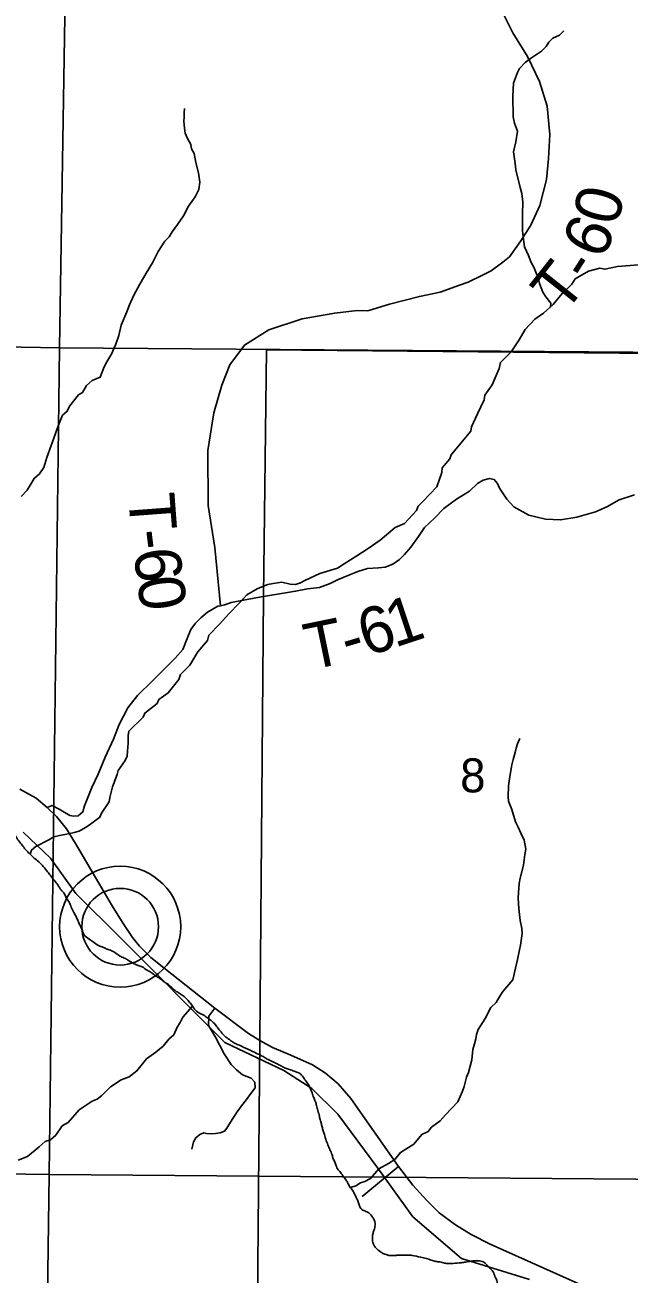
# Model space of a CAD drawing. Extents: x 0 to 191, y 0 to 55.
# Drawn here: x 148.459 to 148.831, y 19.371 to 20.139 of the extents above; entities that cross this region are included whole.
import ezdxf

# ---------------------------------------------------------------- set-up
doc = ezdxf.new("R2010")
doc.units = 0
for name, color, linetype in [('GM_X_Corporation', 7, 'Continuous'), ('GM_X_Minor_River', 7, 'Continuous'), ('GM_X_Rail_Line', 7, 'Continuous'), ('GM_X_Section_Text', 7, 'Continuous'), ('GM_X_State_Route', 7, 'Continuous'), ('GM_X_Township_Road', 7, 'Continuous'), ('GM_X_Township_Road_Text', 7, 'Continuous'), ('GM_X_Unincorporated', 7, 'Continuous'), ('GM_X_Unincorporated_Location', 7, 'Continuous')]:
    doc.layers.add(name, color=color, linetype=linetype)

msp = doc.modelspace()

# ---------------------------------------------------------------- linework, layer by layer
at = {"layer": 'GM_X_Corporation'}
msp.add_lwpolyline([(149.91399, 21.66502), (149.90793, 21.52064), (149.51981, 21.52878), (149.51691, 21.19595), (149.51218, 20.83281), (149.50627, 20.43118), (149.50476, 20.23346), (149.50131, 20.01186), (149.50163, 19.93083), (149.34339, 19.93301), (149.01689, 19.93705), (148.9116, 19.93663), (148.60782, 19.9395), (148.60599, 19.78812), (148.60369, 19.51507), (148.60074, 19.16895), (148.59988, 18.92019), (148.47736, 18.92075), (148.46737, 18.92047), (148.27305, 18.92256)], dxfattribs=at)
for points in [[(147.98029, 20.45945), (148.48878, 20.45041), (148.48051, 19.94079), (147.97486, 19.94949)], [(148.48878, 20.45041), (148.99652, 20.44079), (148.99576, 19.93695), (148.48051, 19.94079)], [(148.46264, 18.61761), (150.07549, 18.61761), (150.07549, 20.00272), (149.87411, 20.00453), (149.74513, 20.00707), (149.50131, 20.01186), (149.50163, 19.93083), (149.34339, 19.93301), (149.01689, 19.93705), (148.9116, 19.93663), (148.60782, 19.9395), (148.60599, 19.78812), (148.60369, 19.51507), (148.60074, 19.16895), (148.59988, 18.92019), (148.47736, 18.92075), (148.46737, 18.92047)], [(147.97486, 19.94949), (148.48051, 19.94079), (148.47431, 19.43234), (147.97418, 19.43959)], [(148.48051, 19.94079), (148.99576, 19.93695), (148.98937, 19.42831), (148.47431, 19.43234)], [(147.97418, 19.43959), (148.47431, 19.43234), (148.4672, 18.92122), (147.9684, 18.92831)], [(148.47431, 19.43234), (148.98937, 19.42831), (148.98207, 18.917), (148.4672, 18.92122)]]:
    msp.add_lwpolyline(points, close=True, dxfattribs=at)
at = {"layer": 'GM_X_Minor_River'}
for points in [[(148.78237, 19.96581), (148.7826, 19.96813), (148.77951, 19.97208), (148.77776, 19.97491), (148.7756, 19.9804), (148.77499, 19.98324), (148.77224, 19.99043), (148.77049, 19.99326), (148.76891, 19.99761), (148.76638, 20.0029), (148.7655, 20.01069), (148.76528, 20.01316), (148.76521, 20.01791), (148.76532, 20.02305), (148.76541, 20.03028), (148.76476, 20.03559), (148.76376, 20.03938), (148.76114, 20.05019), (148.7607, 20.05417), (148.75965, 20.06139), (148.76107, 20.06749), (148.76211, 20.07397), (148.76033, 20.07889), (148.75952, 20.08288), (148.75933, 20.09543), (148.75978, 20.10361), (148.76215, 20.11011), (148.76343, 20.1126), (148.76698, 20.11627), (148.77016, 20.11878), (148.7769, 20.12325), (148.77989, 20.12615), (148.78136, 20.12864), (148.78398, 20.13115), (148.78792, 20.13311), (148.79072, 20.13562)], [(148.45697, 19.8493), (148.4607, 19.85316), (148.46494, 19.86044), (148.46831, 19.86334), (148.4709, 19.86718), (148.47289, 19.87329), (148.47543, 19.88074), (148.47707, 19.88514), (148.47961, 19.89221), (148.48235, 19.89928), (148.48515, 19.9016), (148.48699, 19.90505), (148.49219, 19.91178), (148.49482, 19.91334), (148.49722, 19.91756), (148.50077, 19.92065), (148.50566, 19.92281), (148.50802, 19.92912), (148.50968, 19.93218), (148.51282, 19.93736), (148.5141, 19.94042), (148.5152, 19.9431), (148.51701, 19.94826), (148.51862, 19.95475), (148.5221, 19.96297), (148.52374, 19.96718), (148.5263, 19.97311), (148.52998, 19.97982), (148.53386, 19.98672), (148.53774, 19.99305), (148.54123, 19.99994), (148.5453, 20.00628), (148.5481, 20.00898), (148.54995, 20.01205), (148.5531, 20.01665), (148.5568, 20.02203), (148.55993, 20.02797), (148.56401, 20.03354), (148.56621, 20.03814), (148.5669, 20.04271), (148.56606, 20.04841), (148.56446, 20.05466), (148.56343, 20.06035), (148.56168, 20.06318), (148.56126, 20.06584), (148.55932, 20.06942), (148.55794, 20.07283), (148.55752, 20.07586), (148.55708, 20.08023), (148.55723, 20.08271), (148.55719, 20.08518), (148.55753, 20.08785)], [(148.4626, 19.62934), (148.46339, 19.6319), (148.466, 19.63403), (148.47408, 19.63813), (148.47708, 19.64007), (148.48066, 19.64088), (148.48614, 19.64191), (148.48972, 19.64272), (148.49274, 19.64352), (148.49649, 19.64586), (148.49893, 19.64722), (148.50548, 19.65207), (148.50639, 19.65455), (148.5112, 19.66165), (148.51154, 19.66432), (148.51315, 19.6708), (148.51607, 19.67845), (148.5166, 19.68092), (148.52105, 19.68707), (148.52214, 19.68975), (148.52248, 19.69279), (148.52278, 19.69774), (148.52272, 19.7023), (148.52325, 19.70497), (148.53201, 19.71365), (148.53311, 19.71613), (148.54059, 19.72194), (148.54169, 19.72443), (148.5475, 19.7285), (148.554, 19.73677), (148.5549, 19.73982), (148.56068, 19.7456), (148.56567, 19.75385), (148.57163, 19.76078), (148.57233, 19.76402), (148.57924, 19.77096), (148.58445, 19.77693), (148.59134, 19.78387), (148.59581, 19.78887), (148.60219, 19.79257), (148.60501, 19.79375), (148.60878, 19.79514), (148.61199, 19.79575), (148.61727, 19.79659), (148.6224, 19.79552), (148.62562, 19.79518), (148.62882, 19.79618), (148.63145, 19.79773), (148.64066, 19.80205), (148.65159, 19.80524), (148.65552, 19.80796), (148.6634, 19.81282), (148.67033, 19.81729), (148.67782, 19.82253), (148.68698, 19.83026), (148.69262, 19.83281), (148.70008, 19.84071), (148.70117, 19.84339), (148.70397, 19.84628), (148.71254, 19.85534), (148.71563, 19.86413), (148.71596, 19.86698), (148.72061, 19.87256), (148.72133, 19.87505), (148.72728, 19.88216), (148.73342, 19.88948), (148.73395, 19.89215), (148.73761, 19.90018), (148.74165, 19.9088), (148.74218, 19.91166), (148.74662, 19.91799), (148.75083, 19.92813), (148.75172, 19.93176), (148.75825, 19.93832), (148.76325, 19.94561), (148.76694, 19.95213), (148.7729, 19.9583), (148.77814, 19.96199), (148.78412, 19.96739), (148.7897, 19.97413), (148.79548, 19.97992), (148.7977, 19.98318), (148.80577, 19.98786), (148.81274, 19.98967), (148.81578, 19.98914), (148.8237, 19.99077), (148.83656, 19.9919)], [(148.65944, 19.42433), (148.66284, 19.42542), (148.66566, 19.42717), (148.66829, 19.42816), (148.67186, 19.42992), (148.67688, 19.43588), (148.68289, 19.4392), (148.68683, 19.44172), (148.69017, 19.44595), (148.69842, 19.45101), (148.70345, 19.45697), (148.7072, 19.45892), (148.70925, 19.46142), (148.71468, 19.4653), (148.71784, 19.46914), (148.72548, 19.47704), (148.72841, 19.48354), (148.72932, 19.48641), (148.73074, 19.49232), (148.73203, 19.49519), (148.734, 19.50281), (148.73466, 19.50929), (148.73574, 19.51272), (148.73664, 19.51578), (148.73698, 19.51844), (148.73807, 19.5215), (148.74233, 19.5284), (148.74582, 19.5351), (148.74899, 19.53818), (148.7514, 19.54202), (148.75325, 19.5449), (148.75939, 19.5522), (148.76099, 19.55926), (148.76223, 19.5646), (148.76347, 19.57051), (148.76399, 19.57336), (148.76502, 19.5806), (148.76479, 19.58364), (148.76377, 19.58857), (148.76291, 19.59597), (148.76262, 19.60243), (148.76276, 19.60585), (148.76325, 19.61137), (148.76377, 19.61461), (148.76592, 19.62262), (148.76677, 19.6291), (148.76729, 19.63252), (148.76626, 19.63802), (148.7645, 19.64199), (148.76255, 19.64595), (148.76099, 19.64935), (148.7586, 19.65692), (148.75664, 19.66203), (148.75641, 19.66469), (148.75669, 19.67134), (148.75736, 19.67725), (148.75824, 19.68182), (148.75877, 19.6843), (148.75948, 19.68754), (148.76074, 19.69193), (148.76127, 19.6946), (148.76217, 19.69727), (148.76364, 19.70053)], [(148.56235, 19.53592), (148.55648, 19.52923), (148.55483, 19.52578), (148.55298, 19.5231), (148.55097, 19.51832), (148.54779, 19.51561), (148.54426, 19.51138), (148.53977, 19.50771), (148.53415, 19.50345), (148.52821, 19.49614), (148.52334, 19.49247), (148.51845, 19.49069), (148.51189, 19.48622), (148.50667, 19.48102), (148.50386, 19.4787), (148.50066, 19.47752), (148.4926, 19.47208), (148.48591, 19.46439), (148.48215, 19.46224), (148.47845, 19.45668), (148.47508, 19.45378), (148.4717, 19.4526), (148.46815, 19.44951), (148.46085, 19.44351), (148.45521, 19.44115)]]:
    msp.add_lwpolyline(points, dxfattribs=at)
for points in [[(148.27162, 19.69552), (148.27391, 19.69364), (148.27601, 19.69137), (148.27906, 19.6893), (148.28155, 19.68704), (148.28422, 19.68516), (148.2867, 19.68327), (148.28918, 19.68158), (148.29184, 19.68008), (148.29756, 19.67708), (148.3006, 19.67539), (148.30327, 19.67464), (148.30669, 19.67353), (148.30954, 19.67279), (148.31182, 19.67223), (148.31429, 19.67149), (148.31676, 19.67131), (148.31941, 19.67209), (148.32188, 19.67249), (148.32453, 19.67326), (148.32718, 19.67423), (148.32964, 19.67519), (148.33285, 19.67655), (148.33607, 19.67752), (148.33854, 19.67791), (148.34309, 19.67794), (148.34632, 19.67777), (148.3486, 19.67741), (148.35107, 19.67724), (148.3543, 19.67688), (148.35695, 19.67689), (148.35923, 19.6771), (148.36435, 19.67713), (148.36682, 19.67677), (148.37005, 19.67603), (148.37233, 19.67509), (148.37519, 19.67435), (148.37766, 19.67361), (148.37994, 19.67305), (148.3826, 19.67231), (148.38564, 19.67176), (148.38811, 19.6714), (148.39191, 19.67066), (148.39571, 19.67012), (148.39894, 19.66976), (148.40122, 19.66939), (148.40388, 19.66884), (148.40635, 19.66829), (148.40863, 19.66773), (148.41148, 19.66661), (148.41529, 19.66531), (148.41833, 19.66419), (148.42081, 19.66287), (148.42424, 19.66081), (148.42691, 19.6593), (148.42919, 19.65856), (148.43243, 19.65611), (148.43491, 19.6548), (148.43719, 19.65386), (148.43986, 19.65236), (148.44253, 19.65048), (148.44559, 19.64727), (148.44788, 19.64557), (148.45036, 19.64331), (148.45265, 19.64162), (148.45456, 19.63897), (148.45667, 19.63613), (148.45859, 19.63368), (148.46107, 19.63084), (148.46337, 19.62858), (148.46566, 19.62651), (148.46852, 19.62406), (148.47062, 19.62179), (148.4733, 19.61858), (148.47522, 19.61612), (148.47752, 19.6131), (148.47962, 19.61045), (148.48154, 19.60743), (148.48365, 19.60497), (148.4848, 19.60251), (148.48653, 19.59986), (148.48788, 19.59683), (148.48942, 19.59361), (148.49077, 19.59096), (148.49192, 19.5885), (148.49308, 19.58585), (148.49443, 19.5832), (148.49578, 19.57979), (148.49883, 19.57715), (148.50131, 19.57546), (148.50456, 19.5732), (148.5076, 19.57208), (148.50988, 19.57095), (148.51255, 19.57002), (148.51521, 19.56852), (148.51826, 19.56645), (148.52112, 19.56514)], [(148.52112, 19.56514), (148.5236, 19.56364), (148.52893, 19.56101), (148.5314, 19.56008), (148.53445, 19.55801), (148.53693, 19.5567), (148.53979, 19.55444), (148.54208, 19.55312), (148.54494, 19.55086), (148.54761, 19.54917), (148.55009, 19.54691), (148.55238, 19.54502), (148.55486, 19.54352), (148.55715, 19.54182), (148.55963, 19.53937), (148.56155, 19.5371), (148.56308, 19.53484), (148.56557, 19.53219), (148.56861, 19.53069), (148.57128, 19.529), (148.57376, 19.52712), (148.57644, 19.52448), (148.57835, 19.52202), (148.58046, 19.51938), (148.58294, 19.51692), (148.5858, 19.51485), (148.58809, 19.51316), (148.59037, 19.51222), (148.59361, 19.51073), (148.59932, 19.50811), (148.60161, 19.50698), (148.60408, 19.50586), (148.60637, 19.50454), (148.60885, 19.50304), (148.61208, 19.50154), (148.61475, 19.50023), (148.61722, 19.49892), (148.61951, 19.49779), (148.62198, 19.49705), (148.62483, 19.49593), (148.62712, 19.49518), (148.62941, 19.49349), (148.63151, 19.49065), (148.63324, 19.4882), (148.63594, 19.48252), (148.6369, 19.47967), (148.63787, 19.4774), (148.63865, 19.47475), (148.63943, 19.47172), (148.6404, 19.46811), (148.64099, 19.46546), (148.64176, 19.46299), (148.64235, 19.46053), (148.64313, 19.45807), (148.64429, 19.45409), (148.64565, 19.45049), (148.64681, 19.44765), (148.64816, 19.44443), (148.64893, 19.44196), (148.65009, 19.4395), (148.65086, 19.43723), (148.6524, 19.43477), (148.65432, 19.43231), (148.65623, 19.42967), (148.65776, 19.4274), (148.65911, 19.42475), (148.66103, 19.42229), (148.66237, 19.41964), (148.66372, 19.4168), (148.66469, 19.41434), (148.66546, 19.41207), (148.66775, 19.41019), (148.67004, 19.40925), (148.67252, 19.4068), (148.67405, 19.40453), (148.67464, 19.40188), (148.67428, 19.39902), (148.67354, 19.39674), (148.67299, 19.39446), (148.673, 19.39218), (148.67378, 19.38915), (148.67589, 19.3865), (148.67856, 19.38443), (148.68142, 19.38312), (148.6837, 19.38257), (148.68692, 19.38259), (148.6892, 19.38279), (148.6947, 19.38283), (148.69736, 19.38265), (148.70268, 19.38155), (148.7061, 19.38081), (148.70914, 19.37969), (148.712, 19.37895), (148.71446, 19.37859), (148.71732, 19.37785), (148.71959, 19.37767), (148.72263, 19.37769)], [(148.72263, 19.37769), (148.72756, 19.37811), (148.73022, 19.3785), (148.73363, 19.3791), (148.73628, 19.3793), (148.7397, 19.37913), (148.74236, 19.37782), (148.74466, 19.37537), (148.74714, 19.37254), (148.7485, 19.36932), (148.74965, 19.36648), (148.74836, 19.36153), (148.7463, 19.35829), (148.74345, 19.3577), (148.73834, 19.35653), (148.73569, 19.35556), (148.73229, 19.35345), (148.72909, 19.34982), (148.72721, 19.34696), (148.72497, 19.34239), (148.72234, 19.3382), (148.72065, 19.33515), (148.7184, 19.33229), (148.71557, 19.32923), (148.71293, 19.32693), (148.70992, 19.32349), (148.70728, 19.32082), (148.70389, 19.31757), (148.70087, 19.31489), (148.69767, 19.31183), (148.69408, 19.30896), (148.6903, 19.30628), (148.68747, 19.30474), (148.68482, 19.30339), (148.68161, 19.30129), (148.67916, 19.29937), (148.67651, 19.29783), (148.67368, 19.2963), (148.67141, 19.29552), (148.66687, 19.29246), (148.66386, 19.28921), (148.6614, 19.28767), (148.65916, 19.28348), (148.65614, 19.28099), (148.65257, 19.27527), (148.65031, 19.27355), (148.64881, 19.27088), (148.64636, 19.26821), (148.64391, 19.26572), (148.64164, 19.26476), (148.63843, 19.26227), (148.63541, 19.26035), (148.63239, 19.25862), (148.62993, 19.25747), (148.62672, 19.25536), (148.62332, 19.25325), (148.62048, 19.25171), (148.61803, 19.24998), (148.61576, 19.24864), (148.61311, 19.24729), (148.60989, 19.24613), (148.60686, 19.24535), (148.60383, 19.24495), (148.59776, 19.24491), (148.59415, 19.24584), (148.5913, 19.2462), (148.58788, 19.24694), (148.58522, 19.24749), (148.58275, 19.24785), (148.58028, 19.24784), (148.57762, 19.24858), (148.57534, 19.24894), (148.57306, 19.24988), (148.5702, 19.25157), (148.56754, 19.25212), (148.56373, 19.25343)]]:
    msp.add_spline(points, degree=3, dxfattribs=at)
at = {"layer": 'GM_X_Rail_Line'}
msp.add_lwpolyline([(148.45823, 19.64287), (148.47503, 19.62698), (148.49064, 19.6051), (148.51818, 19.57796), (148.58216, 19.5135), (148.61856, 19.49636), (148.63577, 19.48518), (148.65175, 19.46957), (148.67637, 19.43636), (148.69778, 19.40637), (148.72775, 19.38066), (148.76951, 19.3678)], dxfattribs=at)
at = {"layer": 'GM_X_State_Route'}
for points in [[(148.45613, 19.66936), (148.46622, 19.66376), (148.47302, 19.65817), (148.4787, 19.65254), (148.48484, 19.64497), (148.49054, 19.63587), (148.51302, 19.59771), (148.51982, 19.58674), (148.52552, 19.57808), (148.52986, 19.57276), (148.53671, 19.56591), (148.54471, 19.55944), (148.57608, 19.53465)], [(148.57608, 19.53465), (148.5968, 19.51908), (148.60379, 19.5148), (148.61161, 19.51053), (148.6229, 19.50581), (148.63617, 19.49978), (148.64418, 19.49463), (148.65186, 19.48815), (148.65964, 19.47905), (148.68903, 19.43727), (148.69781, 19.42587), (148.70636, 19.41632), (148.71404, 19.40876), (148.72413, 19.40141), (148.73378, 19.39549), (148.74529, 19.38957), (148.81131, 19.36007)]]:
    msp.add_lwpolyline(points, dxfattribs=at)
at = {"layer": 'GM_X_Township_Road'}
msp.add_line((148.6666, 19.41878), (148.68903, 19.43727), dxfattribs=at)
for points in [[(148.75231, 19.99283), (148.75315, 19.99345), (148.75727, 19.99676), (148.76412, 20.00658), (148.77041, 20.0162), (148.77589, 20.02828), (148.77997, 20.04434), (148.78125, 20.05729), (148.78213, 20.07196), (148.78048, 20.08943), (148.77565, 20.10456), (148.76835, 20.11984), (148.75934, 20.13451), (148.74771, 20.15808), (148.74337, 20.1776), (148.7416, 20.19126), (148.74477, 20.20482), (148.75051, 20.21367), (148.76023, 20.22203), (148.76849, 20.22788), (148.77538, 20.23543), (148.77722, 20.23869), (148.77902, 20.24462)], [(148.6707, 19.96372), (148.68351, 19.96766), (148.70185, 19.97236), (148.71472, 19.97507), (148.72643, 19.97927), (148.7319, 19.98108), (148.74056, 19.98542), (148.74602, 19.98818), (148.75231, 19.99283)], [(148.57951, 19.78208), (148.57602, 19.81796), (148.57194, 19.84375), (148.57171, 19.8776), (148.57547, 19.90087), (148.58048, 19.91788), (148.58539, 19.93034), (148.59429, 19.94248), (148.60932, 19.95188), (148.62972, 19.95852), (148.64979, 19.96211), (148.66363, 19.96369), (148.66972, 19.96342), (148.6707, 19.96372)], [(148.60365, 19.78739), (148.60609, 19.78785), (148.62571, 19.79109), (148.63309, 19.79255), (148.64048, 19.79344), (148.64709, 19.79584), (148.65161, 19.79802), (148.6584, 19.80099), (148.66406, 19.80318), (148.66992, 19.805), (148.67674, 19.8055), (148.68072, 19.80595), (148.68544, 19.80775), (148.68957, 19.81068), (148.69275, 19.81358), (148.69665, 19.81822), (148.70129, 19.82477), (148.70498, 19.83035), (148.71115, 19.83597), (148.71693, 19.84197), (148.72462, 19.84762), (148.7327, 19.85253), (148.73755, 19.85737), (148.74113, 19.85933), (148.74491, 19.86035), (148.74777, 19.85983), (148.7499, 19.8574), (148.75109, 19.85456), (148.75559, 19.84761), (148.75985, 19.84293), (148.76906, 19.83777), (148.77936, 19.83548), (148.78868, 19.83489), (148.79872, 19.83659), (148.81006, 19.83984), (148.81704, 19.843), (148.82475, 19.84733), (148.83419, 19.85035)], [(148.47302, 19.65817), (148.47617, 19.65923), (148.48034, 19.65715), (148.48703, 19.65309), (148.48933, 19.65276), (148.49208, 19.65298), (148.49493, 19.65539), (148.49604, 19.6591), (148.5004, 19.67039), (148.50443, 19.67864), (148.50862, 19.68898), (148.51373, 19.7001), (148.51737, 19.7091), (148.52269, 19.71946), (148.52864, 19.72698), (148.53779, 19.73589), (148.54563, 19.74383), (148.55179, 19.74984), (148.55644, 19.75524), (148.55917, 19.76195), (148.56135, 19.7675), (148.56412, 19.77154), (148.56749, 19.77464), (148.57161, 19.77814), (148.578, 19.78187), (148.57951, 19.78208), (148.58235, 19.78271), (148.58613, 19.7841), (148.60365, 19.78739)], [(148.57608, 19.53465), (148.57246, 19.52983), (148.57213, 19.52412), (148.57641, 19.51678), (148.58178, 19.50669), (148.58617, 19.50011), (148.58935, 19.49671), (148.59319, 19.49364), (148.59834, 19.49155), (148.60075, 19.48914), (148.60086, 19.48563), (148.59821, 19.48223), (148.59561, 19.47858), (148.59246, 19.47453), (148.58986, 19.47087), (148.58708, 19.46683), (148.58468, 19.46298), (148.58358, 19.46087), (148.58209, 19.45914), (148.57945, 19.45795), (148.57661, 19.45752), (148.57414, 19.45747), (148.57091, 19.45761), (148.56938, 19.45796), (148.56693, 19.45697), (148.5645, 19.45502), (148.56302, 19.45252), (148.56196, 19.44794)]]:
    msp.add_lwpolyline(points, dxfattribs=at)
at = {"layer": 'GM_X_Unincorporated'}
for radius in [0.0372, 0.02358]:
    msp.add_circle((148.5179, 19.58479), radius, dxfattribs=at)
at = {"layer": 'GM_X_Unincorporated_Location'}
msp.add_line((148.5179, 19.58479), (148.5179, 19.58479), dxfattribs=at)

# ---------------------------------------------------------------- texts
at = {"layer": 'GM_X_Section_Text'}
msp.add_text('8', height=0.02093, rotation=0.00001, dxfattribs=at).set_placement((148.72692, 19.66738))
at = {"layer": 'GM_X_Township_Road_Text'}
for s, rotation, p in [('0', 75.6171, (148.82329, 20.01505)), ('6', 65.95303, (148.81444, 19.99414)), ('T', 51.5296, (148.79089, 19.96103)), ('-', 57.36159, (148.80594, 19.98023)), ('T', 274.28532, (148.52284, 19.85053)), ('-', 276.92848, (148.52456, 19.82792)), ('6', 277.30959, (148.526, 19.81614)), ('0', 277.43941, (148.52823, 19.79871)), ('1', 18.36353, (148.68667, 19.75628)), ('6', 17.20145, (148.66935, 19.75092)), ('T', 11.65116, (148.63445, 19.74254)), ('-', 16.62641, (148.65787, 19.74749))]:
    msp.add_text(s, height=0.02841, rotation=rotation, dxfattribs=at).set_placement(p)

doc.saveas('drawing.dxf')
